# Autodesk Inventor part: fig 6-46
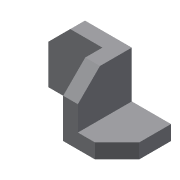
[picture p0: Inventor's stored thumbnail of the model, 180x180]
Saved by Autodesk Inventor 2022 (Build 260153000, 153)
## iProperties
Created: 2001-12
Part Number: fig 6-46
Document SubType Name: Modeling
Designer: Renu Muthoo
Density: 1 g/cm^3
Material: Generic
Appearance: Default
Control State: 0
Master: False
Checked Out: False
Shininess: 77.0
Angle Display Precision: 2
Document Length Units: 11269
Document Angle Units: 11279
Document Time Units: 11290
Document Mass Units: 11283
Document Length Units Precision: 3
Document Angle Units Precision: 2
Density: 0.0
Volumn: 0.0
Area: 0.0
PropertySet Name: Model Information
Author: Renu Muthoo
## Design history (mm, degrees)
node "Sketch1"
sketch "Sketch2"
  geometry: L1 (16.794, 27.142)-(16.794, -22.858); L2 (16.794, -22.858)-(-27.206, -22.858); L3 (-27.206, -22.858)-(-27.206, -10.858); L4 (-27.206, -10.858)-(4.794, -10.858); L5 (4.794, -10.858)-(4.794, 27.142); L6 (4.794, 27.142)-(16.794, 27.142)
  constraints: 12 end point, 4 parallel, 2 perpendicular, 1 vertical
  dimensions: "d0" = 44 distance of L1.end L2.end; "d1" = 50 distance of L1.start L1.end; "d2" = 12 distance of L2.end L3.end
extrude "Extrusion1" new body sketch "Sketch2" distance "d3" = 44; taper "d4" = 0 deg
sketch "Sketch4"
  geometry: L1 (-16.794, -27.142)-(-16.794, 22.858) reference; L2 (27.206, 22.858)-(27.206, 10.858) reference; L3 (-16.794, -27.142)-(-61.001, -27.142); L4 (-61.001, -27.142)-(-61.001, 22.858); L5 (-61.001, 22.858)-(-16.794, 22.858)
  constraints: 6 end point, 2 perpendicular, 1 parallel
extrude "Extrusion3" join sketch "Sketch4" distance "d13" = 12; taper "d14" = 0 deg
chamfer "Chamfer3" distance "d15" = 18; stored, may be unused: second distance "d16" = 2, angle "d17" = 45 deg
body "Solid1"
